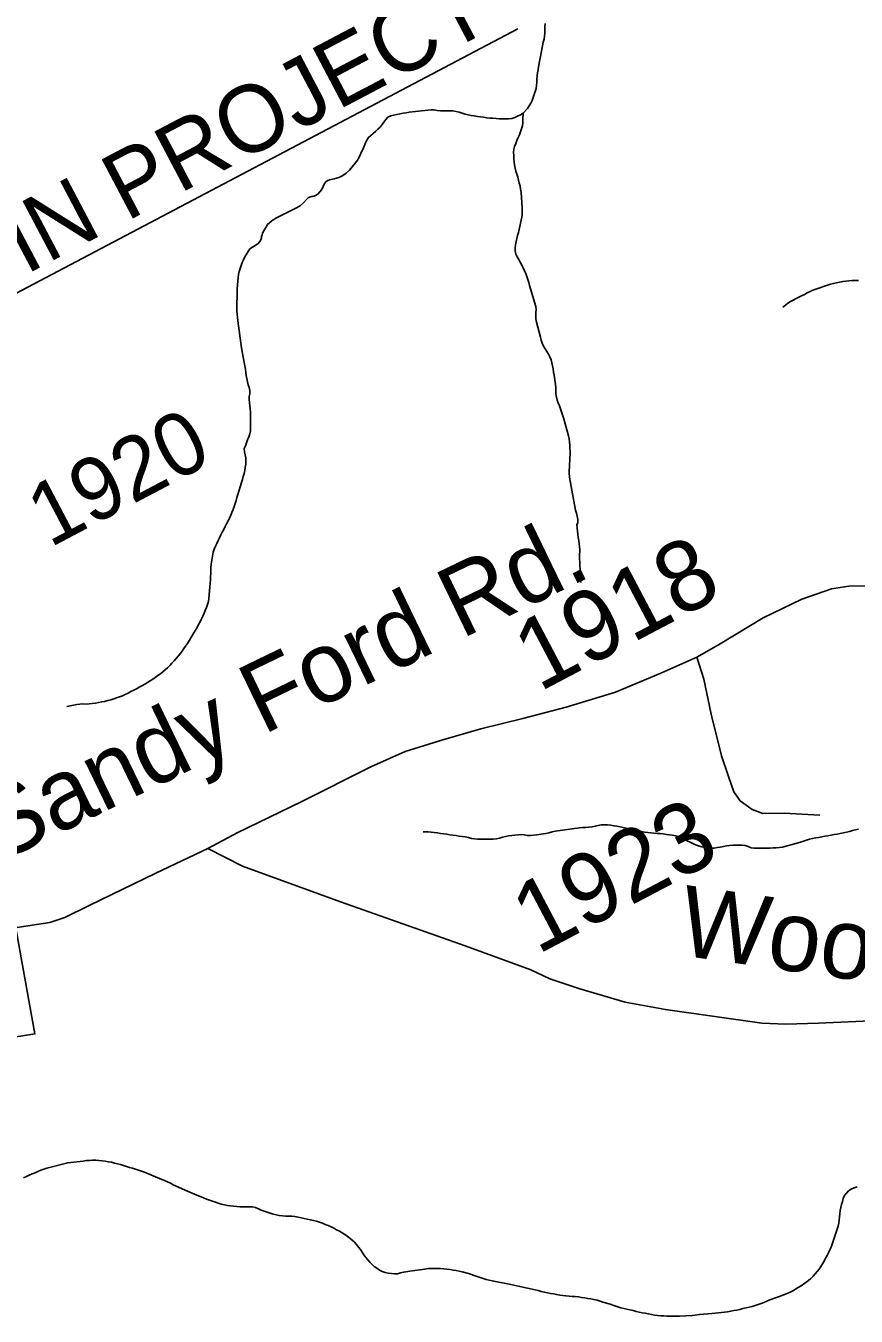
# Model space of a CAD drawing. Extents: x 1379448 to 1382868, y 593769 to 596827.
# Drawn here: x 1379935.9 to 1380109.7, y 595330 to 595600.1 of the extents above; entities that cross this region are included whole.
import ezdxf

# ---------------------------------------------------------------- set-up
doc = ezdxf.new("R2010")
doc.units = 0
for name, color, linetype in [('Old_Level_11', 7, 'Continuous'), ('Old_Level_32', 7, 'Continuous'), ('Old_Level_35', 7, 'Continuous'), ('Old_Level_48', 7, 'Continuous'), ('Old_Level_49', 7, 'Continuous'), ('Old_Level_59', 7, 'Continuous'), ('Old_Level_62', 7, 'Continuous'), ('Old_Level_8', 7, 'Continuous')]:
    doc.layers.add(name, color=color, linetype=linetype)

msp = doc.modelspace()

# ---------------------------------------------------------------- linework, layer by layer
at = {"layer": 'Old_Level_11'}
msp.add_line((1380038.89, 595599.46), (1379894.75, 595523.47), dxfattribs=at)
at = {"layer": 'Old_Level_32'}
for points in [[(1380111.86, 595482.87), (1380108.15, 595482.79), (1380104.54, 595482.29), (1380098.31, 595480.07), (1380090.27, 595476.18), (1380080.91, 595470.55), (1380076.36, 595467.94), (1380068.84, 595464.61), (1380059.31, 595460.63), (1380049.02, 595457.5), (1380039.93, 595455.1), (1380031.17, 595452.94), (1380023.19, 595450.65), (1380015.35, 595448.25), (1380008.12, 595444.98), (1379993.59, 595437.71), (1379980.17, 595431.19), (1379974.02, 595427.95)], [(1379974.02, 595427.95), (1379963.18, 595422.78), (1379949.17, 595415.99), (1379944.08, 595413.49), (1379940.97, 595412.4), (1379937.25, 595411.89), (1379931.41, 595410.98), (1379927.93, 595410.17)], [(1379974.02, 595427.95), (1379981.25, 595424.25), (1380001.77, 595416.74), (1380027.85, 595407.57), (1380041.62, 595402.52), (1380045.63, 595400.67), (1380051.89, 595398.58), (1380061.35, 595395.73), (1380069.79, 595394.19), (1380089.93, 595391.36), (1380094.96, 595391.13), (1380101.8, 595391.36), (1380126.8, 595392.46)]]:
    msp.add_lwpolyline(points, dxfattribs=at)
at = {"layer": 'Old_Level_35'}
msp.add_lwpolyline([(1380076.36, 595467.94), (1380077.8, 595463.37), (1380079.39, 595456.05), (1380081.51, 595447.34), (1380082.95, 595442.97), (1380084.08, 595439.8), (1380085.41, 595437.89), (1380087.97, 595436.1), (1380090.14, 595435.26), (1380094.63, 595435.33), (1380102.09, 595434.87)], dxfattribs=at)
at = {"layer": 'Old_Level_48'}
msp.add_lwpolyline([(1379929.49, 595387.82), (1379937.84, 595389.12), (1379931.29, 595425.64)], dxfattribs=at)
at = {"layer": 'Old_Level_49'}
msp.add_lwpolyline([(1379929.49, 595387.82), (1379937.84, 595389.12), (1379931.29, 595425.64)], dxfattribs=at)
at = {"layer": 'Old_Level_59'}
for points in [[(1379939.07, 595360.58), (1379939.68, 595360.82), (1379940.31, 595360.99), (1379944.71, 595362.15), (1379945.36, 595362.18), (1379947.97, 595362.48), (1379948.61, 595362.6), (1379949.27, 595362.64), (1379949.92, 595362.66), (1379950.59, 595362.66), (1379951.24, 595362.63), (1379951.89, 595362.56), (1379952.54, 595362.47), (1379953.19, 595362.37), (1379953.84, 595362.24), (1379954.48, 595362.09), (1379955.11, 595361.93), (1379955.75, 595361.76), (1379956.38, 595361.57), (1379957.01, 595361.38), (1379957.63, 595361.18), (1379958.26, 595360.98), (1379958.88, 595360.78), (1379959.51, 595360.57), (1379960.13, 595360.36), (1379960.75, 595360.15), (1379964.39, 595358.66), (1379964.98, 595358.4), (1379965.58, 595358.13), (1379966.18, 595357.85), (1379966.77, 595357.56), (1379969.77, 595356.21), (1379971.26, 595355.58)], [(1379935.47, 595358.97), (1379936.06, 595359.25), (1379936.66, 595359.53), (1379937.26, 595359.8), (1379937.86, 595360.07), (1379938.47, 595360.33), (1379939.07, 595360.58)], [(1380106.25, 595351.47), (1380106.34, 595352.12), (1380106.47, 595352.77), (1380106.62, 595353.4), (1380106.81, 595354.04), (1380107.01, 595354.66), (1380107.29, 595355.26), (1380107.65, 595355.81), (1380108.13, 595356.26), (1380108.68, 595356.6), (1380109.28, 595356.89), (1380109.9, 595357.1)], [(1379971.26, 595355.58), (1379973.13, 595354.8), (1379973.74, 595354.55), (1379974.35, 595354.33), (1379974.98, 595354.11), (1379975.6, 595353.91), (1379976.22, 595353.71), (1379976.85, 595353.51), (1379977.48, 595353.34), (1379978.13, 595353.22), (1379978.78, 595353.13), (1379979.43, 595353.06), (1379980.08, 595353), (1379980.74, 595352.95), (1379981.4, 595352.94), (1379982.06, 595352.95), (1379982.71, 595352.95), (1379983.36, 595352.89), (1379984.01, 595352.75), (1379984.6, 595352.48), (1379985.21, 595352.22), (1379985.82, 595351.99), (1379986.44, 595351.78), (1379987.07, 595351.58), (1379987.7, 595351.4), (1379988.34, 595351.25), (1379988.98, 595351.13), (1379989.64, 595351.04), (1379990.29, 595350.99), (1379990.95, 595350.97), (1379991.6, 595350.94), (1379992.26, 595350.88), (1379992.9, 595350.78), (1379993.55, 595350.65), (1379994.19, 595350.51), (1379994.83, 595350.37), (1379995.47, 595350.22), (1379996.11, 595350.06), (1379996.74, 595349.89), (1379997.37, 595349.7), (1379997.99, 595349.49), (1379998.6, 595349.25), (1379999.21, 595349), (1379999.81, 595348.73), (1380000.4, 595348.44), (1380000.98, 595348.14), (1380001.55, 595347.82), (1380002.12, 595347.48), (1380002.67, 595347.12), (1380003.21, 595346.75), (1380003.74, 595346.36), (1380004.25, 595345.95), (1380004.73, 595345.5), (1380005.17, 595345.01), (1380005.59, 595344.5), (1380005.98, 595343.98), (1380006.31, 595343.41), (1380006.66, 595342.85), (1380007.07, 595342.34), (1380007.5, 595341.84), (1380007.94, 595341.36), (1380008.86, 595340.46), (1380009.38, 595340.05), (1380009.94, 595339.7), (1380010.52, 595339.38), (1380011.13, 595339.15), (1380011.77, 595339.02), (1380012.43, 595338.95), (1380013.09, 595338.92), (1380013.75, 595338.92), (1380014.38, 595339.1), (1380015.02, 595339.25), (1380016.3, 595339.46), (1380019.47, 595339.91), (1380020.12, 595340), (1380020.78, 595340.03), (1380021.44, 595340.04), (1380022.09, 595340.03), (1380022.75, 595340.01), (1380023.41, 595339.97), (1380024.06, 595339.9), (1380024.71, 595339.81), (1380025.36, 595339.7), (1380026, 595339.58), (1380026.65, 595339.45), (1380027.28, 595339.32), (1380028.55, 595339), (1380029.17, 595338.79), (1380029.79, 595338.57), (1380030.4, 595338.35), (1380031.02, 595338.12), (1380031.64, 595337.91), (1380032.27, 595337.72), (1380032.9, 595337.55), (1380033.55, 595337.41), (1380037.41, 595336.65), (1380039.34, 595336.28), (1380042.53, 595335.54), (1380043.17, 595335.38), (1380043.81, 595335.22)], [(1380043.81, 595335.22), (1380044.45, 595335.08), (1380045.09, 595334.94), (1380045.73, 595334.81), (1380046.38, 595334.69), (1380047.03, 595334.57), (1380047.67, 595334.46), (1380048.32, 595334.36), (1380048.97, 595334.27), (1380049.63, 595334.21), (1380050.28, 595334.17), (1380050.93, 595334.12), (1380051.59, 595334.06), (1380052.24, 595333.97), (1380052.89, 595333.87), (1380053.53, 595333.76), (1380054.18, 595333.64), (1380054.82, 595333.5), (1380055.47, 595333.36), (1380056.1, 595333.19), (1380056.72, 595332.99), (1380057.98, 595332.6), (1380059.19, 595332.2), (1380059.81, 595331.97), (1380060.44, 595331.79), (1380061.08, 595331.64), (1380061.72, 595331.49), (1380062.36, 595331.34), (1380063, 595331.19), (1380063.64, 595331.05), (1380064.28, 595330.91), (1380064.92, 595330.77), (1380065.56, 595330.64), (1380066.21, 595330.51), (1380066.85, 595330.39), (1380067.5, 595330.28), (1380068.15, 595330.19), (1380068.8, 595330.12), (1380069.46, 595330.08), (1380070.11, 595330.06), (1380070.77, 595330.04), (1380071.43, 595330.03), (1380072.09, 595330.04), (1380072.74, 595330.05), (1380075.35, 595330.21), (1380076, 595330.28), (1380076.91, 595330.4), (1380079.53, 595330.63), (1380080.18, 595330.69), (1380080.83, 595330.75), (1380081.49, 595330.82), (1380082.14, 595330.89), (1380082.78, 595330.98), (1380083.44, 595331.09), (1380084.08, 595331.2), (1380084.72, 595331.32), (1380085.37, 595331.46), (1380086.01, 595331.61), (1380086.65, 595331.76), (1380087.29, 595331.92), (1380087.92, 595332.07), (1380088.56, 595332.25), (1380089.18, 595332.45), (1380089.8, 595332.68), (1380090.41, 595332.91), (1380091.01, 595333.19), (1380091.6, 595333.45), (1380092.82, 595333.91), (1380093.46, 595334.07), (1380095.28, 595334.78), (1380095.87, 595335.06), (1380096.45, 595335.37), (1380097.03, 595335.69), (1380097.59, 595336.02), (1380098.16, 595336.36), (1380099.74, 595337.49), (1380100.24, 595337.92), (1380100.7, 595338.39), (1380101.14, 595338.88), (1380101.56, 595339.38), (1380101.96, 595339.9), (1380102.32, 595340.45), (1380102.66, 595341.01), (1380102.98, 595341.58), (1380103.3, 595342.15), (1380103.62, 595342.73), (1380103.93, 595343.31), (1380104.22, 595343.9), (1380104.47, 595344.51), (1380104.7, 595345.13), (1380104.91, 595345.74), (1380105.13, 595346.37), (1380105.33, 595346.99), (1380105.54, 595347.61), (1380105.74, 595348.24), (1380105.92, 595348.87), (1380106.05, 595349.51), (1380106.13, 595350.16), (1380106.19, 595350.82), (1380106.25, 595351.47)]]:
    msp.add_lwpolyline(points, dxfattribs=at)
at = {"layer": 'Old_Level_62'}
for points in [[(1380044.59, 595600.59), (1380044.55, 595599.93), (1380044.54, 595599.27), (1380044.52, 595598.62), (1380044.48, 595597.96), (1380044.39, 595597.31), (1380044.22, 595596.68), (1380043.85, 595594.76), (1380043.25, 595591.54), (1380043.13, 595590.89), (1380043.02, 595590.25), (1380042.93, 595589.6), (1380042.89, 595588.94), (1380042.87, 595588.28), (1380042.83, 595587.62), (1380042.72, 595586.98), (1380042.54, 595586.35), (1380042.34, 595585.72), (1380042.12, 595585.1), (1380041.87, 595584.48), (1380041.59, 595583.89), (1380041.29, 595583.32), (1380040.9, 595582.79), (1380040.02, 595581.79)], [(1380040.02, 595581.79), (1380039.43, 595581.48), (1380038.85, 595581.17), (1380038.25, 595580.9), (1380037.63, 595580.72), (1380036.97, 595580.65), (1380036.31, 595580.64), (1380035.66, 595580.64), (1380035, 595580.65), (1380034.34, 595580.68), (1380033.69, 595580.74), (1380033.03, 595580.8), (1380032.38, 595580.87), (1380031.73, 595580.96), (1380031.08, 595581.04), (1380030.43, 595581.14), (1380029.78, 595581.24), (1380029.13, 595581.35), (1380028.49, 595581.47), (1380027.85, 595581.64), (1380027.22, 595581.83), (1380026.59, 595582.02), (1380025.96, 595582.18), (1380025.31, 595582.29), (1380024.66, 595582.33), (1380024, 595582.31), (1380023.34, 595582.29), (1380022.69, 595582.3), (1380022.03, 595582.38), (1380021.38, 595582.49), (1380020.73, 595582.5), (1380020.08, 595582.46), (1380019.42, 595582.4), (1380018.77, 595582.33), (1380018.11, 595582.25), (1380017.46, 595582.16), (1380016.16, 595581.99), (1380015.51, 595581.89), (1380014.87, 595581.79), (1380014.22, 595581.67), (1380013.57, 595581.56), (1380012.93, 595581.42), (1380012.29, 595581.25), (1380011.71, 595580.98), (1380011.26, 595580.48), (1380010.88, 595579.95), (1380010.5, 595579.41), (1380010.07, 595578.91), (1380009.62, 595578.44), (1380009.14, 595577.99), (1380008.65, 595577.56), (1380008.15, 595577.14), (1380007.65, 595576.73), (1380007.32, 595576.17), (1380007.01, 595575.58), (1380006.61, 595574.57)], [(1380040.02, 595581.79), (1380039.97, 595580.47), (1380039.94, 595579.81), (1380039.85, 595579.16), (1380039.7, 595578.54), (1380039.48, 595577.92), (1380039.24, 595577.3), (1380038.98, 595576.7), (1380038.72, 595576.09), (1380038.47, 595575.48), (1380038.23, 595574.87), (1380038.03, 595574.25), (1380038, 595573.59), (1380038.04, 595572.93), (1380038.08, 595572.28), (1380038.13, 595571.62), (1380038.21, 595570.97), (1380038.31, 595570.32), (1380038.47, 595569.69), (1380038.66, 595569.06), (1380038.87, 595568.44), (1380039.06, 595567.81), (1380039.21, 595567.17), (1380039.36, 595566.53), (1380039.48, 595565.88), (1380039.57, 595565.23), (1380039.84, 595562.02), (1380039.84, 595561.36), (1380039.82, 595560.7), (1380039.74, 595560.05), (1380039.62, 595559.4), (1380039.48, 595558.77), (1380039.33, 595558.12), (1380039.17, 595557.48), (1380039.01, 595556.85), (1380038.85, 595556.21), (1380038.69, 595555.57), (1380038.55, 595554.93), (1380038.43, 595554.29), (1380038.37, 595553.63), (1380038.36, 595552.98), (1380038.5, 595552.33), (1380038.78, 595551.75), (1380039.1, 595551.17), (1380039.42, 595550.6), (1380039.72, 595550.01), (1380040.02, 595549.43), (1380040.31, 595548.84), (1380040.57, 595548.23), (1380040.78, 595547.62), (1380040.98, 595546.99), (1380041.17, 595546.36), (1380041.36, 595545.73), (1380042.64, 595541.32), (1380042.73, 595540.71), (1380042.69, 595540.05), (1380042.66, 595539.39), (1380042.67, 595538.74), (1380042.79, 595538.09), (1380043.61, 595534.93), (1380043.78, 595534.29), (1380043.99, 595533.67), (1380044.27, 595533.08), (1380044.6, 595532.51), (1380044.96, 595531.95), (1380045.31, 595531.39), (1380045.62, 595530.81), (1380045.84, 595530.2), (1380046.01, 595529.57), (1380046.15, 595528.93), (1380046.28, 595528.29), (1380046.39, 595527.64), (1380046.49, 595526.99), (1380046.77, 595525.03), (1380046.82, 595524.37), (1380046.85, 595523.71), (1380046.88, 595523.05), (1380046.96, 595522.4), (1380047.11, 595521.77), (1380047.33, 595521.16), (1380047.59, 595520.55), (1380048.44, 595518.07), (1380049.48, 595514.28), (1380049.62, 595513.64), (1380049.7, 595512.99), (1380049.76, 595512.34), (1380049.8, 595511.68), (1380049.83, 595511.02), (1380049.82, 595510.37), (1380049.8, 595509.72), (1380049.75, 595509.06), (1380049.71, 595508.4), (1380049.68, 595507.75), (1380049.66, 595507.09), (1380049.67, 595506.43), (1380049.7, 595505.77), (1380049.77, 595505.13), (1380049.89, 595504.48), (1380050.6, 595500.61), (1380051, 595498.71)], [(1380006.61, 595574.57), (1380005.45, 595572.03), (1380003.66, 595569.9), (1380003, 595569.26), (1380002.09, 595568.65), (1380001.42, 595568.34), (1380000.45, 595568.1), (1379999.47, 595567.87), (1379999.16, 595567.73), (1379998.81, 595567.51), (1379998.44, 595567.08), (1379997.86, 595565.85), (1379997.49, 595565.34), (1379997.02, 595564.87), (1379996.58, 595564.58), (1379996.24, 595564.46), (1379995.76, 595564.38), (1379995.31, 595564.26), (1379995.01, 595564.11), (1379994.72, 595563.8), (1379993.97, 595562.98), (1379993.35, 595562.44), (1379992.47, 595561.95), (1379988.39, 595559.89), (1379987.52, 595559.36), (1379986.91, 595558.89), (1379986.54, 595558.5), (1379986.17, 595557.89), (1379985.77, 595557.21), (1379985.5, 595556.73), (1379985.37, 595556.38), (1379985.28, 595556.01), (1379985.26, 595555.7), (1379985.13, 595555.3), (1379984.89, 595554.93), (1379984.5, 595554.49), (1379982.8, 595553.41)], [(1379982.8, 595553.41), (1379982.11, 595552.28), (1379981.78, 595551.72), (1379981.48, 595551.13), (1379981.22, 595550.53), (1379980.99, 595549.92), (1379980.78, 595549.29), (1379980.61, 595548.66), (1379980.46, 595548.02), (1379980.36, 595547.37), (1379980.3, 595546.72), (1379980.18, 595544.99), (1379980.17, 595544.34), (1379980.16, 595543.68), (1379980.14, 595543.02), (1379980.13, 595542.37), (1379980.13, 595541.71), (1379980.13, 595541.05), (1379980.13, 595540.4), (1379980.37, 595537.79), (1379980.63, 595535.86), (1379980.71, 595535.21), (1379981.09, 595532.69), (1379981.44, 595530.75), (1379981.89, 595528.21), (1379981.96, 595527.56), (1379982.06, 595526.91), (1379982.18, 595526.26), (1379982.31, 595525.62), (1379982.46, 595524.98), (1379982.68, 595524.38), (1379982.83, 595523.77), (1379982.85, 595523.1), (1379982.66, 595522.52), (1379982.69, 595521.87), (1379982.77, 595521.22), (1379982.85, 595520.56), (1379982.92, 595519.91), (1379982.95, 595519.25), (1379982.97, 595518.6), (1379982.98, 595517.94), (1379982.98, 595517.29), (1379982.98, 595516.63), (1379982.96, 595515.97), (1379982.93, 595515.32), (1379982.8, 595514.67), (1379982.6, 595514.05), (1379982.36, 595513.44), (1379982.12, 595512.82), (1379981.88, 595512.22), (1379981.66, 595511.6), (1379981.69, 595510.95), (1379981.85, 595510.3), (1379981.98, 595509.66), (1379982, 595509.01), (1379981.95, 595508.35), (1379981.86, 595507.69), (1379981.74, 595507.05), (1379981.6, 595506.41), (1379981.44, 595505.77), (1379981.26, 595505.14), (1379981.07, 595504.51), (1379980.31, 595501.99), (1379980.13, 595501.36), (1379979.94, 595500.74), (1379979.73, 595500.11), (1379979.52, 595499.49), (1379979.3, 595498.87), (1379979.06, 595498.26), (1379978.81, 595497.66), (1379978.54, 595497.06), (1379978.26, 595496.47), (1379977.96, 595495.88), (1379977.67, 595495.29), (1379977.36, 595494.71), (1379977.06, 595494.13), (1379976.76, 595493.55), (1379976.46, 595492.96), (1379976.17, 595492.37), (1379975.88, 595491.78), (1379975.61, 595491.18), (1379975.36, 595490.57), (1379975.15, 595489.95), (1379974.71, 595487.42), (1379974.67, 595486.76), (1379974.65, 595486.11), (1379974.62, 595485.45), (1379974.6, 595484.79), (1379974.56, 595484.13), (1379974.52, 595483.48), (1379974.25, 595480.25), (1379974.14, 595479.61), (1379973.96, 595478.98), (1379973.75, 595478.36), (1379973.5, 595477.75), (1379973.24, 595477.14), (1379972.96, 595476.54), (1379972.69, 595475.95), (1379972.4, 595475.36), (1379972.09, 595474.77)], [(1380110.16, 595546.8), (1380109.51, 595546.79), (1380108.85, 595546.76), (1380108.2, 595546.7), (1380107.54, 595546.64), (1380106.89, 595546.56), (1380106.24, 595546.45), (1380105.59, 595546.33), (1380104.95, 595546.2), (1380104.32, 595546.03), (1380103.7, 595545.83), (1380101.26, 595545), (1380100.66, 595544.74), (1380100.06, 595544.46), (1380099.47, 595544.18), (1380098.88, 595543.88), (1380098.29, 595543.6), (1380097.7, 595543.3), (1380097.12, 595543.01), (1380096.54, 595542.7), (1380095.96, 595542.38), (1380095.4, 595542.05), (1380094.88, 595541.64), (1380094.33, 595541.19)], [(1380051, 595498.71), (1380051.19, 595498.08), (1380051.35, 595497.44), (1380051.44, 595496.78), (1380051.48, 595496.14), (1380051.28, 595495.64), (1380051.32, 595494.99), (1380051.39, 595494.34), (1380051.47, 595493.68), (1380051.55, 595493.03), (1380051.63, 595492.38), (1380051.71, 595491.73), (1380051.79, 595491.08), (1380051.86, 595490.43), (1380051.82, 595489.16), (1380051.86, 595487.19), (1380052.01, 595485.24), (1380052.04, 595484.59), (1380052.07, 595483.58)], [(1379972.09, 595474.77), (1379971.77, 595474.2), (1379971.45, 595473.63), (1379971.11, 595473.07), (1379969.74, 595470.83), (1379969.38, 595470.29), (1379969.01, 595469.75), (1379968.63, 595469.21), (1379968.24, 595468.68), (1379967.83, 595468.17), (1379967.41, 595467.66), (1379966.97, 595467.17), (1379966.52, 595466.69), (1379966.07, 595466.22), (1379965.6, 595465.76), (1379965.12, 595465.31), (1379964.62, 595464.88), (1379964.11, 595464.48), (1379963.57, 595464.09), (1379963.04, 595463.71), (1379962.49, 595463.34), (1379961.95, 595462.98), (1379961.39, 595462.64), (1379960.82, 595462.31), (1379960.25, 595461.98), (1379959.67, 595461.67), (1379959.09, 595461.36), (1379958.52, 595461.05), (1379957.93, 595460.75), (1379957.34, 595460.45), (1379956.75, 595460.17), (1379956.15, 595459.89), (1379955.55, 595459.67), (1379953.7, 595459.04), (1379953.07, 595458.86), (1379952.43, 595458.71), (1379951.79, 595458.58), (1379951.14, 595458.46), (1379950.49, 595458.34), (1379949.85, 595458.24), (1379949.19, 595458.16), (1379948.54, 595458.13), (1379947.88, 595458.16), (1379947.23, 595458.12), (1379946.58, 595458.02), (1379945.93, 595457.91), (1379944.52, 595457.66)], [(1380078.66, 595428.04), (1380078.01, 595428.15), (1380077.37, 595428.28), (1380076.73, 595428.44), (1380076.11, 595428.66), (1380075.51, 595428.93), (1380074.93, 595429.22), (1380074.34, 595429.52), (1380073.75, 595429.81), (1380073.16, 595430.09), (1380072.56, 595430.35), (1380071.93, 595430.55), (1380071.29, 595430.7), (1380070.64, 595430.8), (1380069.99, 595430.88), (1380069.33, 595430.96), (1380068.68, 595431.03), (1380068.03, 595431.09), (1380067.37, 595431.15), (1380066.72, 595431.22), (1380066.07, 595431.29), (1380065.42, 595431.37), (1380064.77, 595431.46), (1380064.12, 595431.57), (1380063.48, 595431.7), (1380062.84, 595431.85), (1380062.2, 595432), (1380061.56, 595432.16), (1380060.92, 595432.32), (1380060.28, 595432.45), (1380059.63, 595432.57), (1380058.99, 595432.68), (1380058.33, 595432.78), (1380057.68, 595432.86), (1380057.03, 595432.89), (1380056.38, 595432.87), (1380055.73, 595432.75), (1380055.09, 595432.59), (1380054.44, 595432.45), (1380053.79, 595432.38), (1380053.14, 595432.33), (1380052.48, 595432.3), (1380051.83, 595432.25), (1380046.69, 595431.51), (1380046.05, 595431.38), (1380045.41, 595431.23), (1380044.77, 595431.09), (1380042.85, 595430.81), (1380041.54, 595430.65), (1380040.89, 595430.62), (1380040.24, 595430.75), (1380039.59, 595430.83), (1380038.94, 595430.8), (1380038.29, 595430.73), (1380037.63, 595430.64), (1380036.98, 595430.54), (1380036.34, 595430.42), (1380035.7, 595430.27), (1380035.06, 595430.11), (1380034.42, 595429.97), (1380033.77, 595429.89), (1380033.11, 595429.86), (1380032.45, 595429.84), (1380031.8, 595429.85), (1380031.14, 595429.87), (1380030.48, 595429.9), (1380029.83, 595429.96), (1380029.18, 595430.04), (1380028.56, 595430.24), (1380027.91, 595430.34), (1380027.27, 595430.43), (1380026.62, 595430.53), (1380025.97, 595430.63), (1380025.32, 595430.72), (1380024.67, 595430.81), (1380024.02, 595430.91), (1380023.37, 595430.99), (1380022.72, 595431.08), (1380022.07, 595431.17), (1380021.41, 595431.26), (1380020.76, 595431.34), (1380020.11, 595431.42), (1380019.06, 595431.42)], [(1380110.2, 595431.98), (1380109.57, 595431.82), (1380108.93, 595431.65), (1380108.29, 595431.5), (1380107.65, 595431.34), (1380107.02, 595431.2), (1380106.37, 595431.06), (1380105.73, 595430.93), (1380105.08, 595430.82), (1380104.43, 595430.7), (1380103.79, 595430.59), (1380103.14, 595430.48), (1380102.49, 595430.36), (1380101.85, 595430.25), (1380101.2, 595430.12), (1380100.56, 595430), (1380099.93, 595429.85), (1380098.06, 595429.26), (1380096.8, 595428.89), (1380094.28, 595428.19), (1380093.63, 595428.11), (1380092.98, 595428.07), (1380092.32, 595428.04), (1380091.67, 595428.01), (1380091, 595427.99), (1380090.35, 595427.98), (1380089.69, 595427.98), (1380089.03, 595427.99), (1380088.38, 595428.01), (1380087.74, 595428.08), (1380087.12, 595428.34), (1380086.5, 595428.54), (1380085.84, 595428.6), (1380085.19, 595428.63), (1380084.53, 595428.63), (1380083.87, 595428.6), (1380083.22, 595428.54), (1380082.57, 595428.45), (1380081.92, 595428.34), (1380081.27, 595428.22), (1380080.62, 595428.11), (1380079.98, 595428.02), (1380079.32, 595427.99), (1380078.66, 595428.04)]]:
    msp.add_lwpolyline(points, dxfattribs=at)

# ---------------------------------------------------------------- texts
at = {"layer": 'Old_Level_11'}
for s, height, rotation, p in [('BEGIN PROJECT', 14, 27.7977, (1379900.85, 595529.45)), ('Sandy Ford Rd.', 14.7638, 25.8015, (1379930.21, 595424.88)), ('Woodlawn Ave.', 14.7638, 351.9985, (1380072.12, 595405.66))]:
    msp.add_text(s, height=height, rotation=rotation, dxfattribs=at).set_placement(p)
at = {"layer": 'Old_Level_8'}
for s, height, p in [('1920', 13.123, (1379940.94, 595490.78)), ('1918', 14.764, (1380043.37, 595460.58)), ('1923', 14.764, (1380042.96, 595405.61))]:
    msp.add_text(s, height=height, rotation=27.7977, dxfattribs=at).set_placement(p)

doc.saveas('drawing.dxf')
